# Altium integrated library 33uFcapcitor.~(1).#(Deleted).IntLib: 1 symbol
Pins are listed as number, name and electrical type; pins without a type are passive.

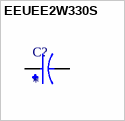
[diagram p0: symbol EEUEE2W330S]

## EEUEE2W330S
designator C?
CAP ALUM 33UF 20% 450V RADIAL; MF: Panasonic; MP: EEU-EE2W330S
footprint CAPPRD750W80D1800H2000
pins: N, P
